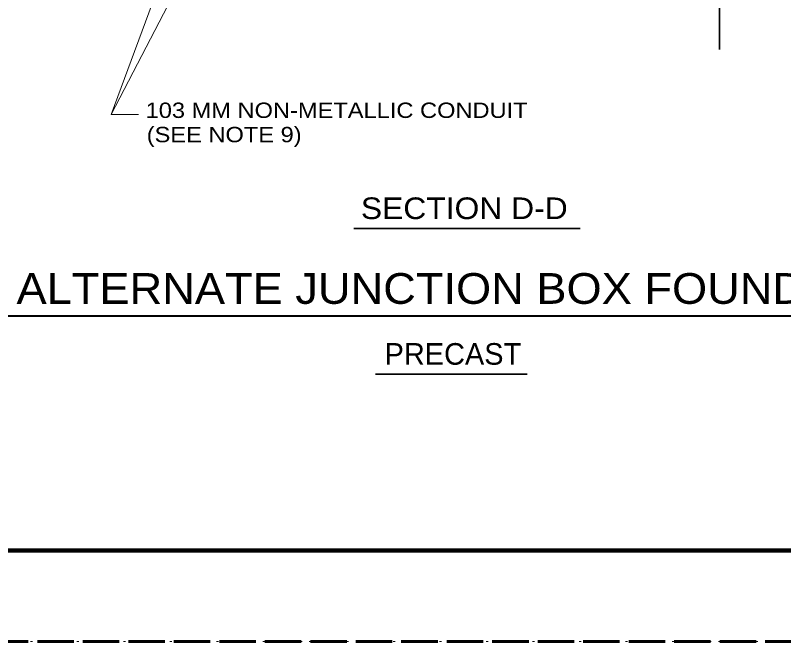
# Model space of a CAD drawing. Extents: x 312583 to 312854, y 144419 to 144597.
# Drawn here: x 312745.36 to 312783.36, y 144418.58 to 144449.56 of the extents above; entities that cross this region are included whole.
import ezdxf
from ezdxf.enums import TextEntityAlignment as Align

# ---------------------------------------------------------------- set-up
doc = ezdxf.new("R2010")
doc.units = 0
doc.header["$LTSCALE"] = 0.3
doc.linetypes.add('DOTTED', pattern=[1.5, 0.3, -1.2])
doc.linetypes.add('LONG_DASHED', pattern=[7.5, 6, -1.5])
for name, color, linetype, lineweight in [('1', 7, 'Continuous', 25), ('2', 7, 'Continuous', 13), ('63', 7, 'DOTTED', 13)]:
    doc.layers.add(name, color=color, linetype=linetype, lineweight=lineweight)

msp = doc.modelspace()

# ---------------------------------------------------------------- linework, layer by layer
at = {"layer": '1', "lineweight": 158}
msp.add_line((312616.5, 144423.0846), (312849, 144423.0846), dxfattribs=at)
at = {"layer": '1', "linetype": 'LONG_DASHED', "lineweight": 60}
msp.add_line((312851.75, 144418.5846), (312583.526, 144418.5846), dxfattribs=at)
at = {"layer": '1', "lineweight": 35}
msp.add_lwpolyline([(312780.1813, 144494.8208), (312780.1813, 144482.4621), (312778.74, 144481.0284), (312781.615, 144481.0284), (312780.1813, 144479.5871), (312780.1813, 144468.2021), (312778.74, 144466.7608), (312781.615, 144466.7608), (312780.1813, 144465.3271), (312780.1813, 144447.8624)], dxfattribs=at)
at = {"layer": '1', "lineweight": 13}
msp.add_lwpolyline([(312757.994, 144465.9788), (312750.0999, 144444.6519), (312757.235, 144458.4041)], dxfattribs=at)
at = {"layer": '2'}
msp.add_line((312751.4416, 144444.6519), (312750.0999, 144444.6519), dxfattribs=at)
at = {"layer": '2', "lineweight": 35}
for p, q in [((312762.1078, 144439.0102), (312773.3048, 144439.0102)), ((312763.1708, 144431.8065), (312770.6827, 144431.8065))]:
    msp.add_line(p, q, dxfattribs=at)
at = {"layer": '2', "lineweight": 40}
msp.add_line((312744.8632, 144434.7007), (312792.0611, 144434.7007), dxfattribs=at)
at = {"layer": '63'}
msp.add_lwpolyline([(312601.2, 144418.5846), (312853.5, 144418.5846), (312853.5, 144596.7846)], dxfattribs=at)

# ---------------------------------------------------------------- texts
at = {"layer": '2', "width": 1.15}
for s, p in [('103 MM NON-METALLIC CONDUIT', (312751.8017, 144444.4826)), ('(SEE NOTE 9)', (312751.8555, 144443.281))]:
    msp.add_text(s, height=0.76, dxfattribs=at).set_placement(p)
at = {"layer": '2', "width": 1.1}
for s, height, p in [('SECTION D-D', 1.07, (312767.5645, 144439.4814)), ('ALTERNATE JUNCTION BOX FOUNDATION', 1.52, (312768.3355, 144435.2893))]:
    msp.add_text(s, height=height, dxfattribs=at).set_placement(p, align=Align.CENTER)
at = {"layer": '2'}
msp.add_text('PRECAST', height=1.07, dxfattribs=at).set_placement((312767.0011, 144432.2777), align=Align.CENTER)

doc.saveas('drawing.dxf')
